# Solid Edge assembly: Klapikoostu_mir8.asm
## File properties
Author: Türk
Template: Iso Assembly.asm
Last saved by: Türk
Revision: 3
Application: Solid Edge
Username: Türk
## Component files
Klapi vedru_mir2.par
Klapipuks.par
Klapp.par
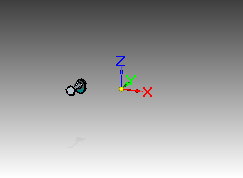
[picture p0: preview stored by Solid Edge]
